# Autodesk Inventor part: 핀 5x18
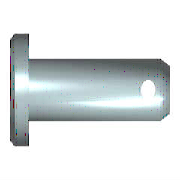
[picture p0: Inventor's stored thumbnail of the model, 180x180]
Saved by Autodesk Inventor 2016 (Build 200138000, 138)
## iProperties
Created: 2012-02
Part Number: 핀 5x18
Material: 강철
Description: 머리가 있는 클레비스 핀
Document SubType Name: Modeling
Standard: ISO 2341
Designer: test
Standard Revision: Second edition 1986-11-01
Standards Organization: ISO
Language: ko-KR
Size Designation: B - 5 x 18
Categories: <MemberInstance><Categories><Category DisplayName="조임쇠" InternalName="e4da775c-781d-43d5-af7c-5136215cf5a6" Mnemonic="FSTN"><Category DisplayName="핀" InternalNa
Density: 7.85 g/cm^3
Appearance: 강철
IsCustomPart: 1
Author: test
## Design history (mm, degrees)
sketch "스케치1"
  geometry: L1 (-1.6, 0)-(-1.6, 4); L2 (-1.6, 4)-(0, 4); L3 (0, 4)-(0, 2.5); L4 (0, 2.5)-(18, 2.5); L5 (18, 2.5)-(18, 0); L6 (-1.6, 0)-(18, 0); L7 (-4, 0)-(17, 0) reference; L8 (0, -0.98)-(0, 3.08) reference; C1 r 0.6 at (15.1, 0)
  constraints: 12 end point, 3 parallel, 2 collinear, 2 perpendicular, 1 centre point, 1 point on line, 1 vertical
  dimensions: "d0" = 5 diameter of L4 L6 (= NND); "d1" = 8 diameter of L2 L6 (= KOD); "d2" = 1.6 distance of L1.end L2.end (= KOH); "d3" = 18 distance of L3.end L4.end (= NLG); "d5" = 2.9 distance from line of L5 C1.centre (= DIST); "d6" = 1.2 diameter of C1 (= BOR)
revolve "본체" stored, may be unused: angle "d4" = 90 deg
extrude "구멍" cut sketch "스케치1" stored distance "d7" = 5 (= NND); taper "d8" = 0 deg
workaxis "Work Axis1"
workplane "Work Plane1"
body "Solid1"
chamfer "모따기1" distance "d9" = 1 (= PHH2); stored, may be unused: angle "d10" = 45 deg (= FAWI2), second distance "d16" = 1 (= PHH2)
chamfer "모따기2" distance "d11" = 2 (= PHH1); stored, may be unused: angle "d12" = 30 deg (= FAWI1), second distance "d17" = 2 (= PHH1)
other parameters: "PHH1" = 2 [user parameter; used in 2 equation terms], "PHH2" = 1 [user parameter; used in 2 equation terms], "KOD" = 8 [user parameter; used in 1 equation term], "KOH" = 1.6 [user parameter; used in 1 equation term], "NND" = 5 [user parameter; used in 2 equation terms], "FAWI1" = 30 deg [user parameter; used in 1 equation term], "FAWI2" = 45 deg [user parameter; used in 1 equation term], "DIST" = 2.9 [user parameter; used in 1 equation term], "BOR" = 1.2 [user parameter; used in 1 equation term], "NLG" = 18 [user parameter; used in 1 equation term], "d13" = 0, "d14" = 0, "d27" = 0, "d28" = 0, "d29" = 0, "d30" = 0, "d31" = 0
